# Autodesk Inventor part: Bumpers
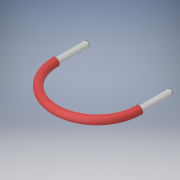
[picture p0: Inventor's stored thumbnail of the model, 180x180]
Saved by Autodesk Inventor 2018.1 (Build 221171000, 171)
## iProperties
Created: 2018-06
Part Number: Bumpers
Material: Generic
Document SubType Name: Modeling
Designer: Ryan
Density: 1 g/cm^3
Appearance: Default
Author: Ryan
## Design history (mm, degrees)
derived "Assembly3 Part out.iam"
sketch "Sketch1"
  geometry: L1 (-38.527, 77.015)-(136.232, 77.015); L2 (136.232, 77.015)-(136.232, -217.058); L3 (136.232, -217.058)-(-38.527, -217.058); L4 (-38.527, -217.058)-(-38.527, 77.015); 1 further point
  constraints: 8 end point, 2 parallel, 1 horizontal, 1 perpendicular
extrude "Extrusion1" cut sketch "Sketch1" distance "d1" = 25.4; taper "d2" = 0 deg
workpoint "Work Point1"
workplane "Work Plane3"
workplane "Work Plane4"
workplane "Work Plane5"
workplane "Work Plane6"
workplane "Work Plane9"
workplane "Work Plane10"
sketch "Sketch2"
  geometry: L1 (-189.977, 45.305)-(102.505, 45.305); L2 (102.505, 45.305)-(102.505, -113.123); L3 (102.505, -113.123)-(-189.977, -113.123); L4 (-189.977, -113.123)-(-189.977, 45.305); 1 further point
  constraints: 8 end point, 2 parallel, 1 horizontal, 1 perpendicular
extrude "Extrusion2" cut sketch "Sketch2" distance "d10" = 328.6125; taper "d11" = 0 deg
sketch "Sketch3"
  geometry: C1 r 4.762 at (0, 0) reference; C2 r 3.175 at (0, 0); C3 r 4.762 at (0, 0) reference; C4 r 3.175 at (0, 0); C5 r 4.762 at (0, 0) reference; C6 r 3.175 at (0, 0); C7 r 4.762 at (0, 0) reference; C8 r 3.175 at (0, 0); 1 further point
  constraints: 4 centre point, 4 coincident
  dimensions: "d12" = 6.35 diameter of C2; "d15" = 6.35 diameter of C6; "d18" = 6.35 diameter of C8; "d19" = 0 distance of C2.centre C8.centre (derived)
extrude "Extrusion4" join sketch "Sketch3" stored distance "d16" = 12.7; taper "d17" = 0 deg
sketch "Sketch6"
  geometry: C1 r 4.762 at (0, 0) reference; C2 r 3.175 at (0, 0); 1 further point
  constraints: 1 centre point, 1 coincident
  dimensions: "d26" = 6.35 diameter of C2
workaxis "Work Axis4"
workaxis "Work Axis5"
workaxis "Work Axis6"
workplane "Work Plane13"
mirror "Mirror1"
sketch "Sketch7"
  geometry: C1 r 4.762 at (0, 0) reference; C2 r 3.175 at (0, 0); C3 r 4.762 at (0, 0) reference; C4 r 3.175 at (0, 0); 1 further point
  constraints: 2 centre point, 2 coincident
  dimensions: "d28" = 6.35 diameter of C2; "d29" = 6.35 diameter of C4
extrude "Extrusion7" join sketch "Sketch7" distance "d30" = 12.7; taper "d31" = 0 deg
mirror "Mirror2"
body "Solid1"
node "Rov v4.2.ipt:1" dims "d0" = 10
node "Motor mount.ipt:1" dims "d0" = 10
node "Motor mount.ipt:2" dims "d0" = 10
node "Motor mount_MIR2.ipt:1" dims "d0" = 10
other parameters: "d4" = 12.7, "d5" = -12.7, "d27" = 90 deg
